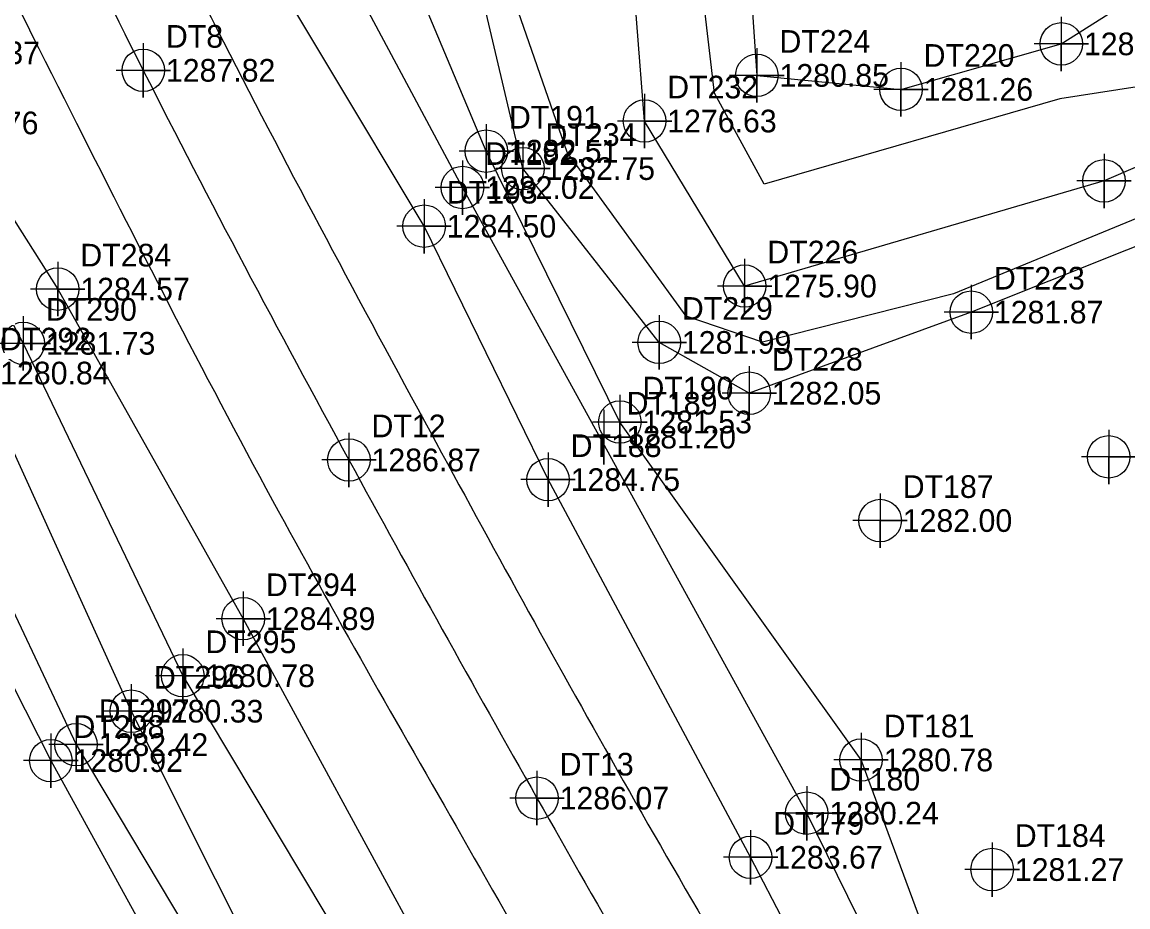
# Model space of a CAD drawing. Extents: x 1394009 to 1394411, y 957864 to 958364.
# Drawn here: x 1394095.7 to 1394217.7, y 958180.8 to 958278.5 of the extents above; entities that cross this region are included whole.
import ezdxf

# ---------------------------------------------------------------- set-up
doc = ezdxf.new("R2010")
doc.units = 0
for name, color, linetype in [('Exist DTM Breakline', 7, 'Continuous'), ('Exist DTM Breakline Cogo Elevation', 7, 'Continuous'), ('Exist DTM Breakline Cogo Number', 7, 'Continuous'), ('Exist DTM Breakline Cogo Point CELL', 7, 'Continuous'), ('Exist DTM Breakline Underwater', 7, 'Continuous'), ('Exist DTM Breakline Underwater Cogo Elevation', 7, 'Continuous'), ('Exist DTM Breakline Underwater Cogo Number', 7, 'Continuous'), ('Exist DTM Breakline Underwater Cogo Point CELL', 7, 'Continuous'), ('Exist DTM Crownline', 7, 'Continuous'), ('Exist DTM Regular Point Cogo Elevation', 7, 'Continuous'), ('Exist DTM Spot Elevation CELL', 7, 'Continuous'), ('Exist DTM Spot Elevation Cogo Elevation', 7, 'Continuous'), ('Exist DTM Spot Elevation Cogo Number', 7, 'Continuous'), ('Exist Hydro Stream or Body of Water', 7, 'Continuous'), ('Exist Roads EOP', 7, 'Continuous'), ('Exist Structure Minor Culvert Topo', 7, 'Continuous'), ('Exist Structure Minor Culvert Topo Terminator', 7, 'Continuous'), ('Exist Structure Minor Footbridge Terminator', 7, 'Continuous'), ('PH Exist DTM NCFMP LIDAR Elevation Point', 7, 'Continuous'), ('Raster_Level_0', 7, 'Continuous')]:
    doc.layers.add(name, color=color, linetype=linetype)

msp = doc.modelspace()

# ---------------------------------------------------------------- linework, layer by layer
at = {"layer": 'Exist DTM Breakline'}
for points in [[(1394242.4363, 958236.4587), (1394250.3213, 958249.8392), (1394247.4683, 958258.6227), (1394226.1736, 958256.7484), (1394200.4578, 958246.4971), (1394175.9465, 958237.5482), (1394166.0162, 958243.1539), (1394150.9651, 958262.3435), (1394145.9876, 958283.4911), (1394149.6991, 958293.4183), (1394147.595, 958317.4165), (1394162.2974, 958343.3573)], [(1394201.5002, 958152.1258), (1394182.2949, 958191.1856), (1394144.2973, 958260.2559), (1394124.9997, 958296.4083), (1394109.3726, 958331.5215)], [(1394190.4005, 958148.8159), (1394191.5413, 958156.6052), (1394176.0985, 958186.3137), (1394153.7403, 958228.0077), (1394140.0661, 958255.9875), (1394118.8047, 958291.5046), (1394102.5433, 958327.8357)], [(1394203.3254, 958156.4773), (1394188.2939, 958197.0575), (1394161.6676, 958234.367), (1394146.9232, 958264.2671), (1394130.3208, 958303.8046)], [(1394183.7059, 958302.6672), (1394175.5913, 958290.3266), (1394176.7902, 958272.6343), (1394192.7029, 958271.0839), (1394210.3962, 958276.1116), (1394227.7375, 958287.1282), (1394241.3942, 958284.8435), (1394266.8472, 958274.7526), (1394273.951, 958265.5798), (1394280.4133, 958252.6154), (1394279.4205, 958214.8325), (1394286.3541, 958194.8367), (1394283.5006, 958151.7161)], [(1394070.2199, 958268.841), (1394083.0781, 958275.1225), (1394099.617, 958249.0394), (1394120.0982, 958212.652), (1394140.7402, 958174.6816), (1394162.1474, 958145.323), (1394171.088, 958138.1508)], [(1394070.1313, 958268.4251), (1394080.9574, 958242.6289), (1394101.6472, 958198.7507), (1394123.0372, 958162.9752), (1394143.223, 958131.4044), (1394156.1703, 958108.6674), (1394147.5951, 958089.3097), (1394152.395, 958060.7909)], [(1394078.4681, 958267.2162), (1394077.4426, 958263.4985), (1394090.7676, 958239.7722), (1394107.7408, 958202.4417), (1394126.2755, 958165.4231), (1394146.8464, 958135.0295)], [(1394078.4815, 958267.2528), (1394082.9126, 958267.3867), (1394095.8187, 958243.0525), (1394113.4272, 958206.3553), (1394134.4907, 958171.1858), (1394155.1759, 958139.8204), (1394165.1856, 958129.7757), (1394177.2665, 958121.2673), (1394190.9858, 958098.52), (1394181.5225, 958090.4285), (1394174.2125, 958080.1878)], [(1394065.3665, 958259.7005), (1394076.2432, 958241.6096), (1394098.862, 958196.9887), (1394119.1062, 958160.1529), (1394140.102, 958128.983), (1394150.6899, 958110.4316), (1394136.5853, 958093.0812), (1394143.0953, 958059.9522)]]:
    msp.add_lwpolyline(points, dxfattribs=at)
at = {"layer": 'Exist DTM Breakline Cogo Point CELL'}
for points in [[(1394210.3962, 958279.1116), (1394210.3962, 958273.1116), (1394210.3962, 958276.1116), (1394213.3962, 958276.1116), (1394207.3962, 958276.1116)], [(1394176.7902, 958275.6343), (1394176.7902, 958269.6343), (1394176.7902, 958272.6343), (1394179.7902, 958272.6343), (1394173.7902, 958272.6343)], [(1394192.7029, 958274.0839), (1394192.7029, 958268.0839), (1394192.7029, 958271.0839), (1394195.7029, 958271.0839), (1394189.7029, 958271.0839)], [(1394146.9232, 958267.2671), (1394146.9232, 958261.2671), (1394146.9232, 958264.2671), (1394149.9232, 958264.2671), (1394143.9232, 958264.2671)], [(1394150.9651, 958265.3435), (1394150.9651, 958259.3435), (1394150.9651, 958262.3435), (1394153.9651, 958262.3435), (1394147.9651, 958262.3435)], [(1394144.2973, 958263.2559), (1394144.2973, 958257.2559), (1394144.2973, 958260.2559), (1394147.2973, 958260.2559), (1394141.2973, 958260.2559)], [(1394140.0661, 958258.9875), (1394140.0661, 958252.9875), (1394140.0661, 958255.9875), (1394143.0661, 958255.9875), (1394137.0661, 958255.9875)], [(1394099.617, 958252.0394), (1394099.617, 958246.0394), (1394099.617, 958249.0394), (1394102.617, 958249.0394), (1394096.617, 958249.0394)], [(1394200.4578, 958249.4971), (1394200.4578, 958243.4971), (1394200.4578, 958246.4971), (1394203.4578, 958246.4971), (1394197.4578, 958246.4971)], [(1394095.8187, 958246.0525), (1394095.8187, 958240.0525), (1394095.8187, 958243.0525), (1394098.8187, 958243.0525), (1394092.8187, 958243.0525)], [(1394166.0162, 958246.1539), (1394166.0162, 958240.1539), (1394166.0162, 958243.1539), (1394169.0162, 958243.1539), (1394163.0162, 958243.1539)], [(1394175.9465, 958240.5482), (1394175.9465, 958234.5482), (1394175.9465, 958237.5482), (1394178.9465, 958237.5482), (1394172.9465, 958237.5482)], [(1394161.6676, 958237.367), (1394161.6676, 958231.367), (1394161.6676, 958234.367), (1394164.6676, 958234.367), (1394158.6676, 958234.367)], [(1394153.7403, 958231.0077), (1394153.7403, 958225.0077), (1394153.7403, 958228.0077), (1394156.7403, 958228.0077), (1394150.7403, 958228.0077)], [(1394120.0982, 958215.652), (1394120.0982, 958209.652), (1394120.0982, 958212.652), (1394123.0982, 958212.652), (1394117.0982, 958212.652)], [(1394113.4272, 958209.3553), (1394113.4272, 958203.3553), (1394113.4272, 958206.3553), (1394116.4272, 958206.3553), (1394110.4272, 958206.3553)], [(1394107.7408, 958205.4417), (1394107.7408, 958199.4417), (1394107.7408, 958202.4417), (1394110.7408, 958202.4417), (1394104.7408, 958202.4417)], [(1394101.6472, 958201.7507), (1394101.6472, 958195.7507), (1394101.6472, 958198.7507), (1394104.6472, 958198.7507), (1394098.6472, 958198.7507)], [(1394098.862, 958199.9887), (1394098.862, 958193.9887), (1394098.862, 958196.9887), (1394101.862, 958196.9887), (1394095.862, 958196.9887)], [(1394188.2939, 958200.0575), (1394188.2939, 958194.0575), (1394188.2939, 958197.0575), (1394191.2939, 958197.0575), (1394185.2939, 958197.0575)], [(1394182.2949, 958194.1856), (1394182.2949, 958188.1856), (1394182.2949, 958191.1856), (1394185.2949, 958191.1856), (1394179.2949, 958191.1856)], [(1394176.0985, 958189.3137), (1394176.0985, 958183.3137), (1394176.0985, 958186.3137), (1394179.0985, 958186.3137), (1394173.0985, 958186.3137)]]:
    msp.add_lwpolyline(points, dxfattribs=at)
for centre in [(1394210.3962, 958276.1116), (1394176.7902, 958272.6343), (1394192.7029, 958271.0839), (1394146.9232, 958264.2671), (1394150.9651, 958262.3435), (1394144.2973, 958260.2559), (1394140.0661, 958255.9875), (1394099.617, 958249.0394), (1394200.4578, 958246.4971), (1394095.8187, 958243.0525), (1394166.0162, 958243.1539), (1394175.9465, 958237.5482), (1394161.6676, 958234.367), (1394153.7403, 958228.0077), (1394120.0982, 958212.652), (1394113.4272, 958206.3553), (1394107.7408, 958202.4417), (1394101.6472, 958198.7507), (1394098.862, 958196.9887), (1394188.2939, 958197.0575), (1394182.2949, 958191.1856), (1394176.0985, 958186.3137)]:
    msp.add_circle(centre, 2.344, dxfattribs=at)
at = {"layer": 'Exist DTM Breakline Underwater'}
msp.add_lwpolyline([(1394229.3063, 958094.7507), (1394267.6222, 958126.159), (1394273.9153, 958153.4417), (1394270.8807, 958172.7151), (1394257.7841, 958202.8194), (1394247.0365, 958219.368), (1394259.7999, 958250.0935), (1394260.5275, 958261.5147), (1394243.0302, 958273.0023), (1394215.1121, 958260.9873), (1394175.4465, 958249.379), (1394164.3967, 958267.5944), (1394161.8631, 958300.0699), (1394178.2103, 958310.6665)], dxfattribs=at)
at = {"layer": 'Exist DTM Breakline Underwater Cogo Point CELL'}
for points in [[(1394164.3967, 958270.5944), (1394164.3967, 958264.5944), (1394164.3967, 958267.5944), (1394167.3967, 958267.5944), (1394161.3967, 958267.5944)], [(1394215.1121, 958263.9873), (1394215.1121, 958257.9873), (1394215.1121, 958260.9873), (1394218.1121, 958260.9873), (1394212.1121, 958260.9873)], [(1394175.4465, 958252.379), (1394175.4465, 958246.379), (1394175.4465, 958249.379), (1394178.4465, 958249.379), (1394172.4465, 958249.379)]]:
    msp.add_lwpolyline(points, dxfattribs=at)
for centre in [(1394164.3967, 958267.5944), (1394215.1121, 958260.9873), (1394175.4465, 958249.379)]:
    msp.add_circle(centre, 2.344, dxfattribs=at)
at = {"layer": 'Exist DTM Crownline'}
msp.add_spline([(1394087.9321, 958316.4176), (1394109.0623, 958273.1922), (1394131.7594, 958230.1822), (1394152.5248, 958192.8438), (1394173.9492, 958155.4634)], degree=3, dxfattribs=at)
at = {"layer": 'Exist DTM Spot Elevation CELL'}
msp.add_lwpolyline([(1394159.9093, 958235.6954), (1394159.9093, 958229.6954), (1394159.9093, 958232.6954), (1394162.9093, 958232.6954), (1394156.9093, 958232.6954)], dxfattribs=at)
at = {"layer": 'Exist Hydro Stream or Body of Water'}
for points in [[(1394221.231, 958104.5797), (1394238.8971, 958116.0346), (1394254.7004, 958129.0614), (1394261.0998, 958155.6228), (1394258.5223, 958177.5159), (1394245.4045, 958205.4301), (1394241.5211, 958222.9502), (1394246.6022, 958237.6666), (1394253.5489, 958252.431), (1394251.9663, 958257.7082), (1394245.398, 958262.4184), (1394226.1093, 958259.8812), (1394198.4822, 958248.5108), (1394177.4215, 958243.2011), (1394168.9777, 958246.0581), (1394155.8669, 958264.1507), (1394149.2709, 958283.1502), (1394154.661, 958297.4554), (1394160.3871, 958316.4078), (1394173.556, 958323.8378)], [(1394231.5705, 958091.2594), (1394270.5171, 958123.5077), (1394277.8383, 958154.0025), (1394278.608, 958197.1243), (1394267.0972, 958226.2539), (1394275.5986, 958257.1902), (1394265.6306, 958269.8313), (1394243.4303, 958275.2121), (1394210.2309, 958270.0539), (1394177.5999, 958260.6264), (1394172.1027, 958270.6648), (1394169.7578, 958290.7959), (1394182.6519, 958307.5361)]]:
    msp.add_lwpolyline(points, dxfattribs=at)
at = {"layer": 'Exist Roads EOP'}
for points in [[(1394096.2145, 958320.2223), (1394117.2204, 958277.6897), (1394140.0936, 958234.4745), (1394160.6957, 958197.1466), (1394182.7363, 958159.1242)], [(1394078.897, 958312.8974), (1394101.0229, 958268.6968), (1394123.3315, 958225.72), (1394144.2526, 958188.5895), (1394165.818, 958150.9033)]]:
    msp.add_spline(points, degree=3, dxfattribs=at)
at = {"layer": 'Exist Structure Minor Culvert Topo Terminator'}
for points in [[(1394109.0623, 958276.1922), (1394109.0623, 958270.1922), (1394109.0623, 958273.1922), (1394112.0623, 958273.1922), (1394106.0623, 958273.1922)], [(1394131.7594, 958233.1822), (1394131.7594, 958227.1822), (1394131.7594, 958230.1822), (1394134.7594, 958230.1822), (1394128.7594, 958230.1822)], [(1394152.5248, 958195.8438), (1394152.5248, 958189.8438), (1394152.5248, 958192.8438), (1394155.5248, 958192.8438), (1394149.5248, 958192.8438)]]:
    msp.add_lwpolyline(points, dxfattribs=at)
for centre in [(1394109.0623, 958273.1922), (1394131.7594, 958230.1822), (1394152.5248, 958192.8438)]:
    msp.add_circle(centre, 2.344, dxfattribs=at)
at = {"layer": 'PH Exist DTM NCFMP LIDAR Elevation Point'}
for points in [[(1394215.6264, 958233.5223), (1394215.6264, 958227.5223), (1394215.6264, 958230.5223), (1394218.6264, 958230.5223), (1394212.6264, 958230.5223)], [(1394190.3969, 958226.4887), (1394190.3969, 958220.4887), (1394190.3969, 958223.4887), (1394193.3969, 958223.4887), (1394187.3969, 958223.4887)], [(1394202.7658, 958187.9615), (1394202.7658, 958181.9615), (1394202.7658, 958184.9615), (1394205.7658, 958184.9615), (1394199.7658, 958184.9615)]]:
    msp.add_lwpolyline(points, dxfattribs=at)
for centre in [(1394215.6264, 958230.5223), (1394190.3969, 958223.4887), (1394202.7658, 958184.9615)]:
    msp.add_circle(centre, 2.344, dxfattribs=at)

# ---------------------------------------------------------------- texts
at = {"layer": 'Exist DTM Breakline Cogo Elevation'}
for s, p in [('1286.37', (1394085.5781, 958273.8725)), ('1280.29', (1394212.8962, 958274.8616)), ('1280.85', (1394179.2902, 958271.3843)), ('1281.26', (1394195.2029, 958269.8339)), ('1282.76', (1394085.4126, 958266.1367)), ('1282.51', (1394149.4232, 958263.0171)), ('1282.75', (1394153.4651, 958261.0935)), ('1282.02', (1394146.7973, 958259.0059)), ('1284.50', (1394142.5661, 958254.7375)), ('1284.57', (1394102.117, 958247.7894)), ('1281.87', (1394202.9578, 958245.2471)), ('1281.73', (1394098.3187, 958241.8025)), ('1281.99', (1394168.5162, 958241.9039)), ('1280.84', (1394093.2676, 958238.5222)), ('1282.05', (1394178.4465, 958236.2982)), ('1281.53', (1394164.1676, 958233.117)), ('1284.75', (1394156.2403, 958226.7577)), ('1284.89', (1394122.5982, 958211.402)), ('1280.78', (1394115.9272, 958205.1053)), ('1280.33', (1394110.2408, 958201.1917)), ('1282.42', (1394104.1472, 958197.5007)), ('1280.78', (1394190.7939, 958195.8075)), ('1280.92', (1394101.362, 958195.7387)), ('1280.24', (1394184.7949, 958189.9356)), ('1283.67', (1394178.5985, 958185.0637))]:
    msp.add_text(s, height=2.5, dxfattribs=at).set_placement(p)
at = {"layer": 'Exist DTM Breakline Cogo Number'}
for s, p in [('DT224', (1394179.2902, 958275.1343)), ('DT220', (1394195.2029, 958273.5839)), ('DT191', (1394149.4232, 958266.7671)), ('DT234', (1394153.4651, 958264.8435)), ('DT192', (1394146.7973, 958262.7559)), ('DT193', (1394142.5661, 958258.4875)), ('DT284', (1394102.117, 958251.5394)), ('DT223', (1394202.9578, 958248.9971)), ('DT290', (1394098.3187, 958245.5525)), ('DT229', (1394168.5162, 958245.6539)), ('DT292', (1394093.2676, 958242.2722)), ('DT228', (1394178.4465, 958240.0482)), ('DT190', (1394164.1676, 958236.867)), ('DT188', (1394156.2403, 958230.5077)), ('DT294', (1394122.5982, 958215.152)), ('DT295', (1394115.9272, 958208.8553)), ('DT296', (1394110.2408, 958204.9417)), ('DT297', (1394104.1472, 958201.2507)), ('DT298', (1394101.362, 958199.4887)), ('DT181', (1394190.7939, 958199.5575)), ('DT180', (1394184.7949, 958193.6856)), ('DT179', (1394178.5985, 958188.8137))]:
    msp.add_text(s, height=2.5, dxfattribs=at).set_placement(p)
at = {"layer": 'Exist DTM Breakline Underwater Cogo Elevation'}
for s, p in [('1276.63', (1394166.8967, 958266.3444)), ('1275.90', (1394177.9465, 958248.129))]:
    msp.add_text(s, height=2.5, dxfattribs=at).set_placement(p)
at = {"layer": 'Exist DTM Breakline Underwater Cogo Number'}
for s, p in [('DT232', (1394166.8967, 958270.0944)), ('DT226', (1394177.9465, 958251.879))]:
    msp.add_text(s, height=2.5, dxfattribs=at).set_placement(p)
at = {"layer": 'Exist DTM Regular Point Cogo Elevation'}
for s, p in [('1282.00', (1394192.8969, 958222.2387)), ('1281.27', (1394205.2658, 958183.7115))]:
    msp.add_text(s, height=2.5, dxfattribs=at).set_placement(p)
at = {"layer": 'Exist DTM Spot Elevation Cogo Elevation'}
msp.add_text('1281.20', height=2.5, dxfattribs=at).set_placement((1394162.4093, 958231.4454))
at = {"layer": 'Exist DTM Spot Elevation Cogo Number'}
msp.add_text('DT189', height=2.5, dxfattribs=at).set_placement((1394162.4093, 958235.1954))
at = {"layer": 'Exist Structure Minor Culvert Topo'}
for s, p in [('DT8', (1394111.5623, 958275.6922)), ('DT12', (1394134.2594, 958232.6822)), ('DT13', (1394155.0248, 958195.3438))]:
    msp.add_text(s, height=2.5, dxfattribs=at).set_placement(p)
at = {"layer": 'Exist Structure Minor Footbridge Terminator'}
for s, p in [('1287.82', (1394111.5623, 958271.9422)), ('1286.87', (1394134.2594, 958228.9322)), ('1286.07', (1394155.0248, 958191.5938))]:
    msp.add_text(s, height=2.5, dxfattribs=at).set_placement(p)
at = {"layer": 'Raster_Level_0'}
for s, p in [('DT187', (1394192.8969, 958225.9887)), ('DT184', (1394205.2658, 958187.4615))]:
    msp.add_text(s, height=2.5, dxfattribs=at).set_placement(p)

doc.saveas('drawing.dxf')
